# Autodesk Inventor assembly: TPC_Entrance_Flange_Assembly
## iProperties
Shininess: 64.0
Length Units: 11269
Angle Units: 11279
Time Units: 11290
Mass Units: 11283
Length Display Precision: 3
Angle Display Precision: 2
Compacted: True
Created: 2004-07
Part Number: TPC_Entrance_Flange_Assembly
Document SubType Name: Assembly
Designer: John Blackburn
Manufacturer: Standard
Standards Organization: Custom
Density: 0.0
Volumn: 0.0
Area: 0.0
PropertySet Name: Model Information
Control State: 0
Master: False
Checked Out: False
Author: John Blackburn
